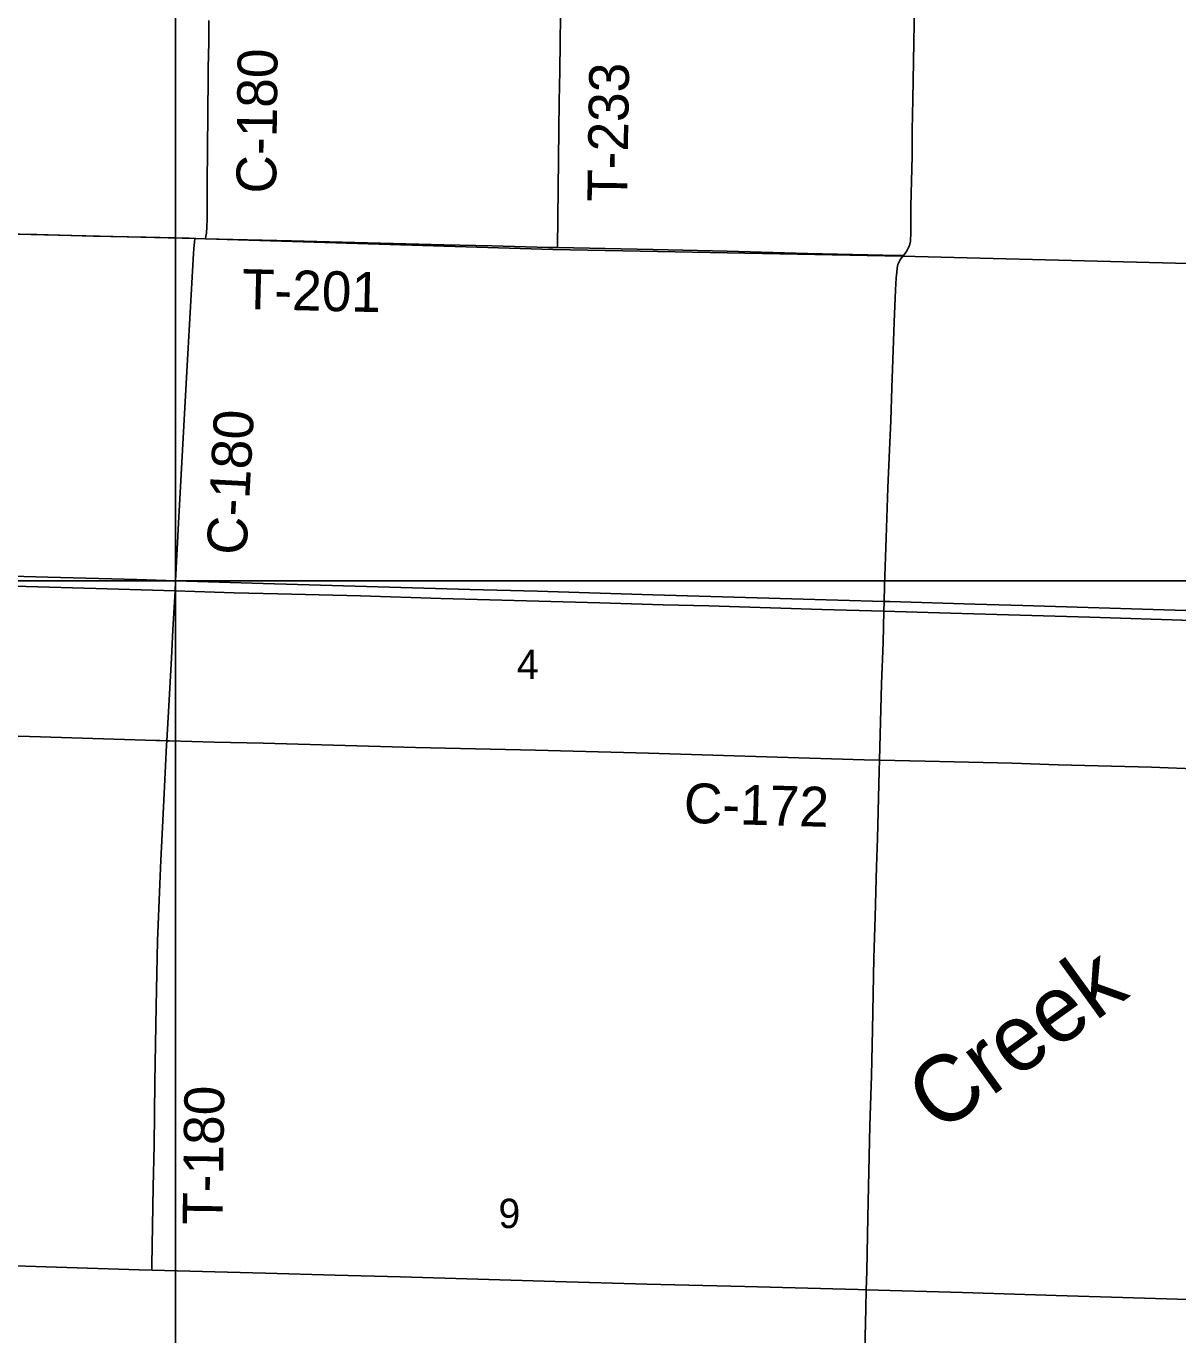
# Model space of a CAD drawing. Extents: x 0 to 68, y 0 to 52.9.
# Drawn here: x 58.195 to 62.532, y 40.611 to 45.541 of the extents above; entities that cross this region are included whole.
import ezdxf

# ---------------------------------------------------------------- set-up
doc = ezdxf.new("R2010")
doc.units = 0
for name, color, linetype in [('Default', 7, 'Continuous'), ('GM_X_County_Road', 7, 'Continuous'), ('GM_X_County_Road_Text', 7, 'Continuous'), ('GM_X_Minor_River_Text', 7, 'Continuous'), ('GM_X_State_Route', 7, 'Continuous'), ('GM_X_Township', 7, 'Continuous'), ('GM_X_Township_Road', 7, 'Continuous'), ('GM_X_Township_Road_Text', 7, 'Continuous')]:
    doc.layers.add(name, color=color, linetype=linetype)

msp = doc.modelspace()

# ---------------------------------------------------------------- linework, layer by layer
at = {"layer": 'Default'}
for p, q in [((58.7572, 34.4614), (58.7572, 52.9414)), ((49.5172, 43.4514), (67.9972, 43.4514))]:
    msp.add_line(p, q, dxfattribs=at)
at = {"layer": 'GM_X_County_Road'}
for points in [[(61.4994, 44.6766), (61.5107, 44.6918), (61.5181, 44.7066), (61.5212, 44.7143), (61.525, 44.7305), (61.5259, 44.7388), (61.527, 44.7554), (61.5271, 44.8622), (61.5311, 45.0509), (61.5321, 45.1493), (61.5339, 45.2641), (61.5394, 45.5512), (61.5425, 45.7235), (61.5481, 45.9449), (61.5479, 45.9779), (61.5478, 45.9931)], [(58.8697, 44.7401), (58.8717, 44.7497), (58.8734, 44.7607), (58.8739, 44.7662), (58.8746, 44.7795), (58.8758, 44.8179), (58.8765, 44.9474), (58.8793, 45.2101), (58.8803, 45.3495), (58.8805, 45.3822), (58.8822, 45.4806), (58.8824, 45.5626)], [(58.7572, 43.4514), (58.7679, 43.6681), (58.7934, 44.1268), (58.8042, 44.3069), (58.8122, 44.4626), (58.825, 44.6838), (58.8264, 44.7015), (58.8289, 44.7285), (58.8301, 44.7413)], [(58.8301, 44.7413), (58.8697, 44.7401)], [(61.4263, 43.3736), (61.4279, 43.4323), (61.4339, 43.6126), (61.4403, 43.8012), (61.4448, 43.9156), (61.4514, 44.0554), (61.4557, 44.1783), (61.4644, 44.4254), (61.4689, 44.5471), (61.4715, 44.5924), (61.4733, 44.614), (61.475, 44.6286), (61.478, 44.6429), (61.4815, 44.6505), (61.4867, 44.6605), (61.4917, 44.6676), (61.4994, 44.6766)], [(58.7554, 43.413), (58.7572, 43.4514)], [(58.7247, 42.8488), (58.7323, 42.9799), (58.7417, 43.1601), (58.7472, 43.2667), (58.7554, 43.413)], [(61.4084, 42.7758), (61.4165, 43.0633), (61.422, 43.2191), (61.4253, 43.3367)], [(61.4253, 43.3367), (61.4263, 43.3736)], [(57.3741, 42.8858), (57.6092, 42.882), (57.9537, 42.8721), (58.2489, 42.8638), (58.6835, 42.8498), (58.6977, 42.8494), (58.7247, 42.8488)], [(58.7247, 42.8488), (58.7346, 42.8484), (58.903, 42.8428), (59.0869, 42.8392), (59.6611, 42.8238), (60.1124, 42.8133), (60.5389, 42.8013), (61.0228, 42.7863), (61.351, 42.7773), (61.4084, 42.7758)], [(61.359, 40.7805), (61.3604, 40.849), (61.3644, 41.0541), (61.3728, 41.3985), (61.378, 41.5871), (61.3819, 41.7594), (61.3875, 42.0301), (61.3918, 42.1859), (61.3971, 42.3745), (61.4005, 42.481), (61.4072, 42.7353), (61.4084, 42.7758)], [(61.4084, 42.7758), (61.5807, 42.7713), (61.9087, 42.7641), (62.081, 42.7585), (62.4337, 42.7489), (62.6223, 42.7413), (62.6961, 42.7404), (62.8355, 42.7456), (62.9175, 42.7446), (63.4999, 42.728), (63.7542, 42.7209), (63.8505, 42.7161), (63.9445, 42.7111), (64.1003, 42.699)], [(61.3254, 39.4564), (61.33, 39.6762), (61.3406, 40.0781), (61.3492, 40.3897), (61.3575, 40.7096), (61.359, 40.7805)]]:
    msp.add_lwpolyline(points, dxfattribs=at)
at = {"layer": 'GM_X_State_Route'}
for points in [[(57.8017, 43.4415), (58.1951, 43.4298), (58.4574, 43.4223), (58.7554, 43.413), (58.9787, 43.4062), (59.143, 43.4019), (59.4533, 43.3942), (59.7567, 43.3852), (60.3554, 43.3677), (60.5933, 43.3608), (60.7655, 43.3564), (61.192, 43.3434), (61.4253, 43.3367), (61.6759, 43.3292), (62.2007, 43.3137), (62.5862, 43.3022), (62.9212, 43.293), (63.0349, 43.2889), (63.4638, 43.2776), (63.5951, 43.2748), (63.8329, 43.2671), (63.9354, 43.2642)], [(58.0953, 43.4695), (58.2762, 43.465), (58.6116, 43.4558), (58.7572, 43.4514), (59.0871, 43.4416), (59.8659, 43.4189), (60.12, 43.4119), (60.3167, 43.4057), (60.5545, 43.3989), (60.948, 43.3875), (61.2513, 43.3786), (61.4263, 43.3736), (61.4481, 43.3731), (61.7678, 43.3636), (61.9481, 43.3587), (62.194, 43.3511), (62.358, 43.346), (62.8081, 43.3315)]]:
    msp.add_lwpolyline(points, dxfattribs=at)
at = {"layer": 'GM_X_Township'}
for points in [[(67.9972, 44.4735), (67.0472, 44.4994), (66.7919, 44.503), (65.491, 44.5506), (64.1656, 44.6005), (63.2588, 44.629), (61.4939, 44.6747), (60.178, 44.6988), (58.8701, 44.7399), (58.8342, 44.7404), (56.8623, 44.7881)], [(56.8623, 44.7881), (58.8342, 44.7404), (58.8701, 44.7399), (60.178, 44.6988), (61.4939, 44.6747), (63.2588, 44.629), (64.1656, 44.6005), (65.491, 44.5506), (66.7919, 44.503), (66.7384, 42.9192), (66.7226, 42.4208), (66.6973, 41.2859), (66.6815, 40.6291), (66.6161, 37.9756), (66.5723, 36.6564), (66.5449, 35.3382), (66.5266, 34.4614)]]:
    msp.add_lwpolyline(points, dxfattribs=at)
at = {"layer": 'GM_X_Township_Road'}
for points in [[(60.1964, 44.7066), (60.2005, 45.1505), (60.2025, 45.2573), (60.2044, 45.3723), (60.2062, 45.4792), (60.2077, 45.5777), (60.2094, 45.6515), (60.2125, 45.8977), (60.2147, 46.0379), (60.217, 46.1665), (60.2183, 46.3099), (60.2215, 46.515), (60.2232, 46.6367), (60.2255, 46.8193), (60.2282, 46.9497), (60.2282, 46.9963), (60.2295, 47.0083), (60.2305, 47.0156), (60.2353, 47.032)], [(56.8815, 44.7858), (57.0209, 44.7825), (57.1849, 44.7792), (57.5376, 44.772), (57.8821, 44.7641), (57.9805, 44.7614), (58.2347, 44.7554), (58.4479, 44.7502), (58.6448, 44.7456), (58.8088, 44.7419), (58.8301, 44.7413)], [(58.8697, 44.7401), (58.9728, 44.737), (59.1942, 44.7319), (59.7683, 44.7175), (59.9487, 44.7131), (60.1619, 44.7072), (60.1964, 44.7066)], [(60.1964, 44.7066), (60.5556, 44.6999), (60.8344, 44.6928), (61.1379, 44.6847), (61.4772, 44.6771), (61.4994, 44.6766)], [(58.6678, 40.8547), (58.6681, 40.8729), (58.6732, 41.1683), (58.6762, 41.3241), (58.6792, 41.562), (58.6843, 41.8488), (58.6899, 42.0949), (58.6985, 42.3081), (58.7025, 42.3982), (58.7068, 42.4966), (58.7156, 42.6768), (58.7238, 42.8325), (58.7247, 42.8488)], [(57.3231, 40.8942), (57.9564, 40.8757), (58.1532, 40.8703), (58.6208, 40.8559), (58.6678, 40.8547)], [(58.6678, 40.8547), (59.0965, 40.8428), (59.359, 40.8351), (59.6051, 40.8287), (60.1876, 40.8111), (60.5322, 40.8018), (60.9013, 40.7923), (61.3279, 40.7814), (61.359, 40.7805)], [(61.359, 40.7805), (61.7217, 40.7698), (62.0744, 40.7583), (62.6978, 40.7396), (62.8701, 40.7359), (62.9768, 40.7333), (63.1491, 40.7307), (63.7809, 40.7182), (64.0385, 40.7129)]]:
    msp.add_lwpolyline(points, dxfattribs=at)

# ---------------------------------------------------------------- texts
at = {"layer": 'Default'}
for s, p in [('4', (60.0428, 43.0817)), ('9', (59.9735, 41.0128))]:
    msp.add_text(s, height=0.1105, rotation=0, dxfattribs=at).set_placement(p)
at = {"layer": 'GM_X_County_Road_Text'}
for s, rotation, p in [('C-180', 89.4476, (59.1363, 44.9096)), ('C-180', 86.9706, (59.0239, 43.5461)), ('C-172', 358.3476, (60.67, 42.5397))]:
    msp.add_text(s, height=0.15, rotation=rotation, dxfattribs=at).set_placement(p)
at = {"layer": 'GM_X_Minor_River_Text'}
msp.add_text('Creek', height=0.25009, rotation=35.8788, dxfattribs=at).set_placement((61.633, 41.3651))
at = {"layer": 'GM_X_Township_Road_Text'}
for s, rotation, p in [('T-233', 89.161, (60.4582, 44.8782)), ('T-201', 358.5957, (59.0057, 44.4759)), ('T-180', 89.1554, (58.9336, 41.0242))]:
    msp.add_text(s, height=0.15, rotation=rotation, dxfattribs=at).set_placement(p)

doc.saveas('drawing.dxf')
